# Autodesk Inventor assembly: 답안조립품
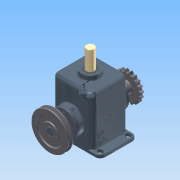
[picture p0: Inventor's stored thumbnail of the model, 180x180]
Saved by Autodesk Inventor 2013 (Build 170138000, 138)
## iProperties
Created: 2015-03
Part Number: 답안조립품
Document SubType Name: Assembly
Designer: Administrator
Mass: 8600.64 g
Surface Area: 4386.44 cm^2
Volume: 1982.5 cm^3
Density: 4.33827 g/cm^3
Author: Administrator
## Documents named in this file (15)
- C:\Documents and Settings\Administrator\바탕 화면\350305V1038\답안조립품.iam
- C:\Documents and Settings\Administrator\바탕 화면\350305V1038\본체.ipt
- C:\Documents and Settings\Administrator\바탕 화면\350305V1038\베어링 6205.ipt
- C:\Documents and Settings\Administrator\바탕 화면\350305V1038\편심축.ipt
- C:\Documents and Settings\Administrator\바탕 화면\350305V1038\멈춤링.ipt
- C:\Documents and Settings\Administrator\바탕 화면\350305V1038\커버.ipt
- C:\Documents and Settings\Administrator\바탕 화면\350305V1038\키 8x8.ipt
- C:\Documents and Settings\Administrator\바탕 화면\350305V1038\오일실.ipt
- C:\Documents and Settings\Administrator\바탕 화면\350305V1038\슬라이드.ipt
- C:\Documents and Settings\Administrator\바탕 화면\350305V1038\부시.ipt
- C:\Documents and Settings\Administrator\바탕 화면\350305V1038\M4x0.5.ipt
- C:\Documents and Settings\Administrator\바탕 화면\350305V1038\V-벨트풀리.ipt
- C:\Documents and Settings\Administrator\바탕 화면\350305V1038\체인 스프로킷.ipt
- C:\Documents and Settings\Administrator\바탕 화면\350305V1038\멈춤나사 M5x0.5.ipt
- C:\Documents and Settings\Administrator\바탕 화면\350305V1038\스프링 - [가변].ipt
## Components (8 placed, 3 different names)
1. V-벨트풀리:1 — 플러쉬:1, 각도:3
2. 5-체인 스프로킷:1 — 플러쉬:2, 각도:4
3. M4x0.5:1
4. M4x0.5:3
5. M4x0.5:4
6. M4x0.5:2
7. M4x0.5:5
8. M4x0.5:6
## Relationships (4: Flush 2, Angle 2)
- 플러쉬:1 [Flush]: V-벨트풀리:1
- 플러쉬:2 [Flush]: 5-체인 스프로킷:1
- 각도:3 [Angle]: V-벨트풀리:1
- 각도:4 [Angle]: 5-체인 스프로킷:1
